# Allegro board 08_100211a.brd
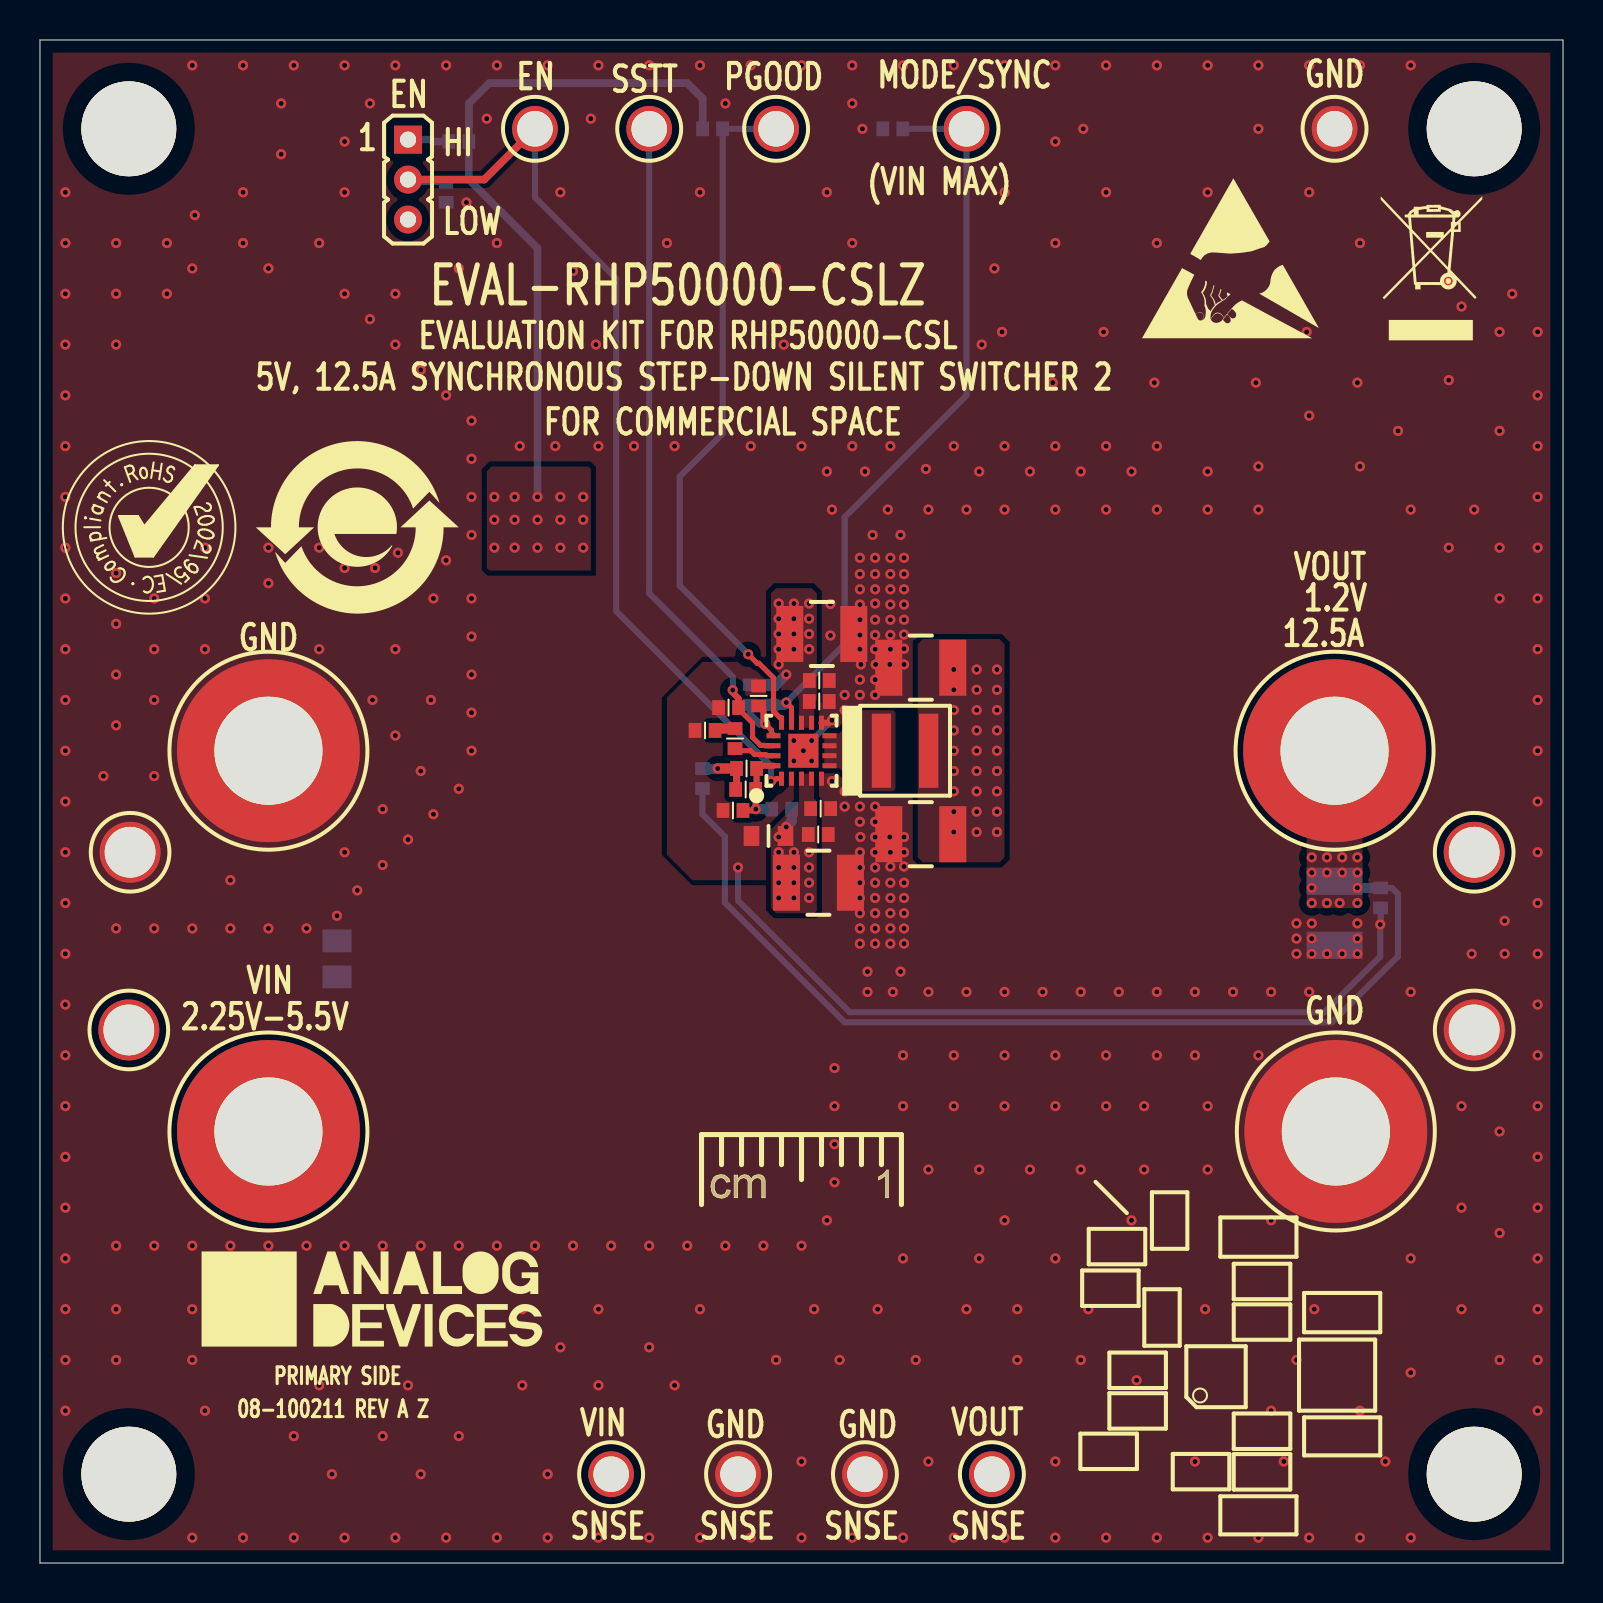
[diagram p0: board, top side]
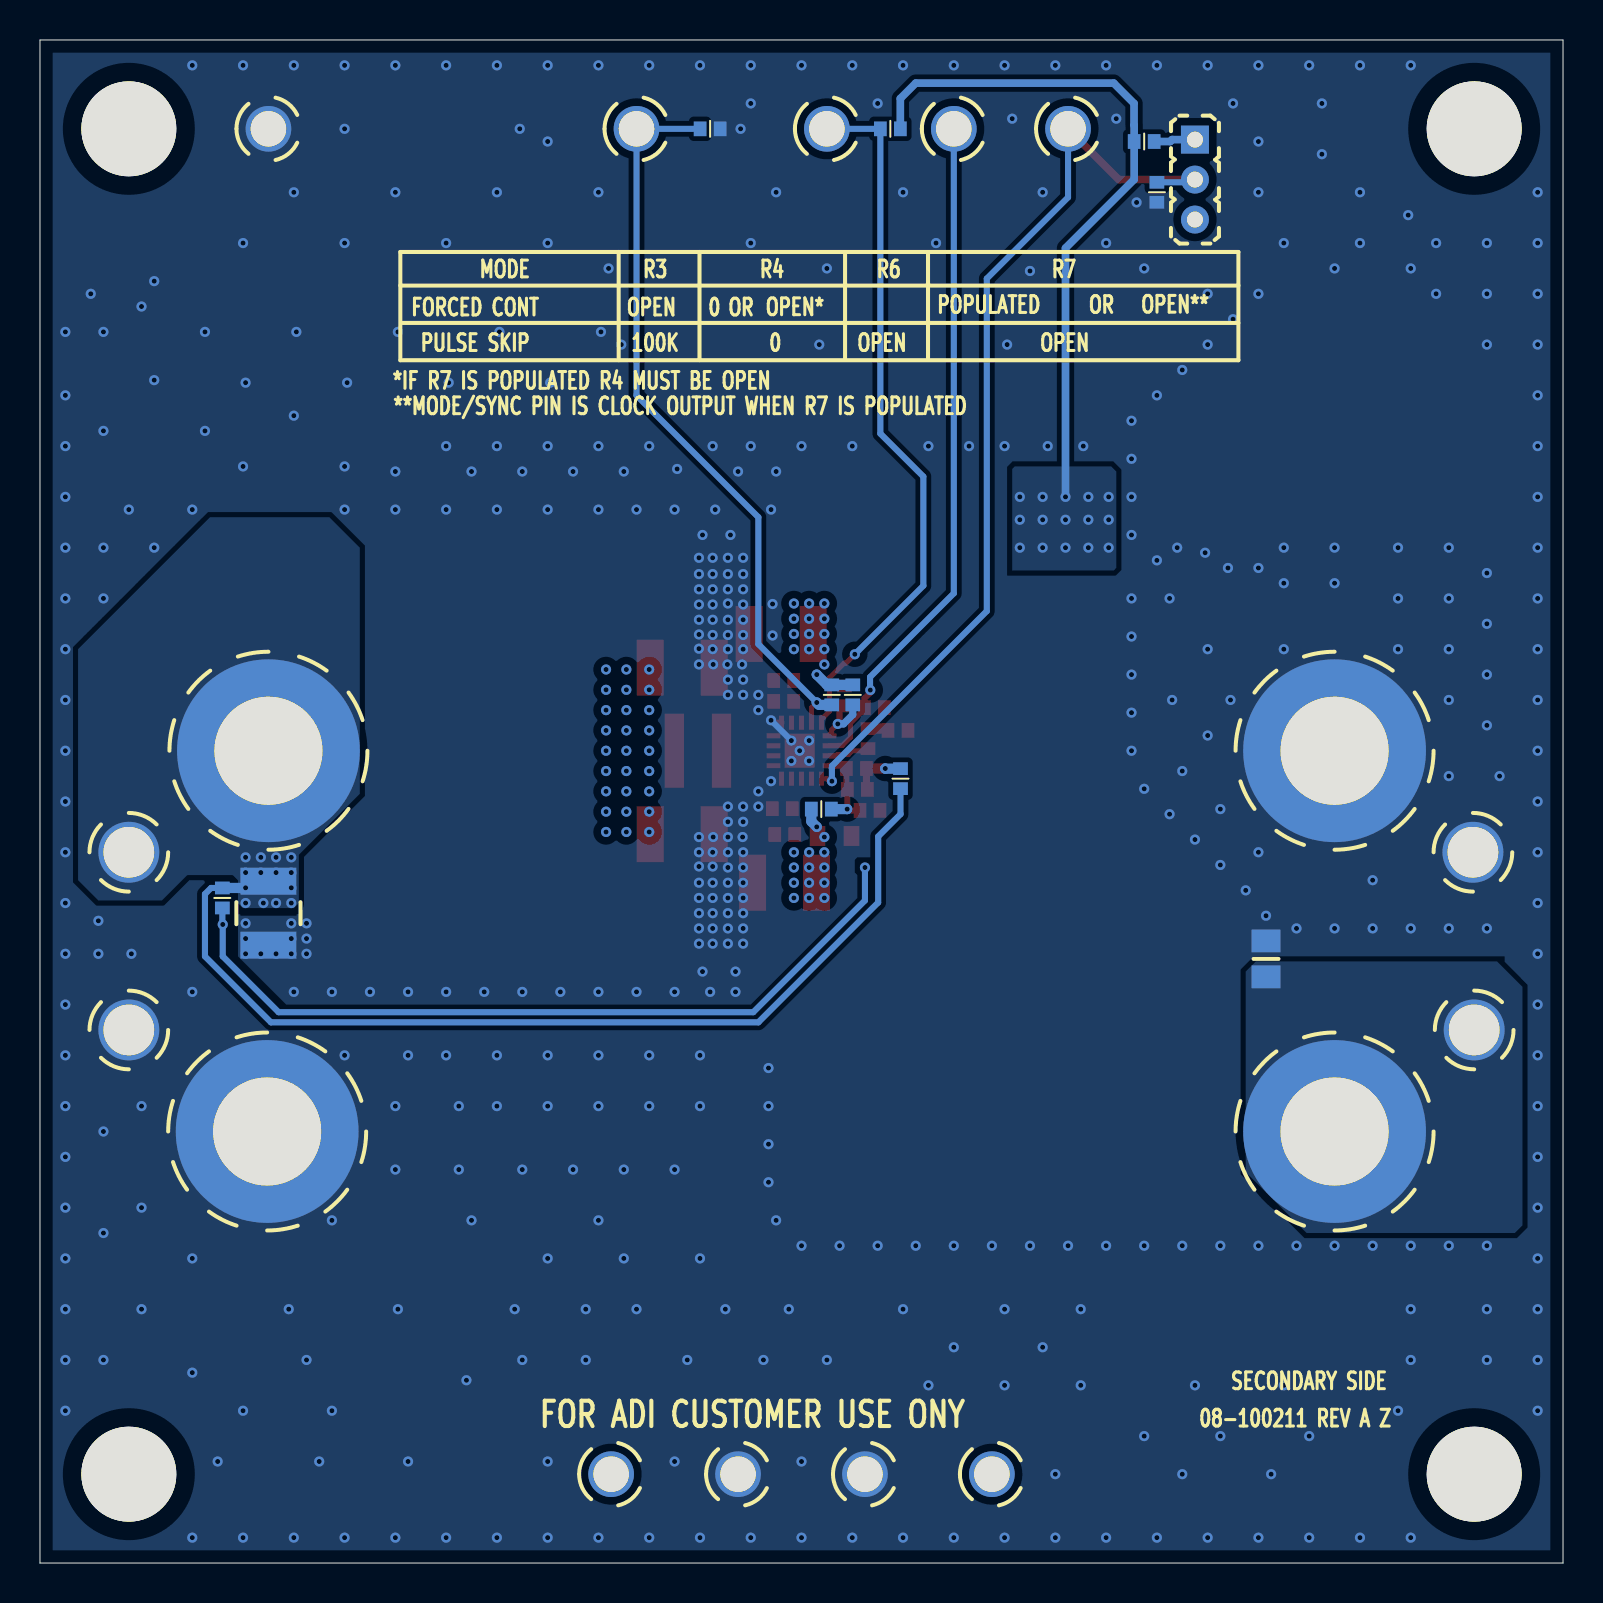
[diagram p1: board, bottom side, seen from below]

Outline 76.2 x 76.2 mm; copper layers: TOP, INTERNAL2, INTERNAL3, BOTTOM. Coordinates in mm from the lower left corner of the outline.
Outline path: 0,76.2 76.2,76.2 76.2,0 0,0 0,76.2

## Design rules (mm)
constraint set DEFAULT: min track width 0.254

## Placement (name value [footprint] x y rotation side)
C2  22UF  [CAP_1210_H110]  38.95 34.04 0 top
C3  22UF  [CAP_1210_H110]  39.12 46.48 0 top
C4  6.8PF  [CAP_0402]  35.31 38.7 0 top
C5  47UF  [CAP_1210_H110]  44.07 44.8 180 top
C6  47UF  [CAP_1210_H110]  44.07 36.46 180 top
C7  0.1UF  [CAP_0402]  67.08 33.27 270 bottom
C8  47UF  [CAP_1210_H110]  64.77 32.51 270 bottom
C9  0.033UF  [CAP_0402]  34.45 42.8 180 top
C11  470PF  [CAP_0402]  33.27 41.66 180 top
C16  10UF  [CAP_0805_H56]  14.86 30.23 90 bottom
C19  0.22UF  [CAP_0402]  38.94 36.45 0 top
C20  0.22UF  [CAP_0402]  38.99 44.15 0 top
C21  1UF  [CAP_0603_H41]  36.45 36.38 180 top
C22  0.1UF  [CAP_0402]  39.06 37.74 0 top
C23  0.1UF  [CAP_0402]  38.99 43.1 0 top
E1  2308-2-00-80-00-00-07-0  [CON_MILMX_2308-2-00-80-00-00-07-0]  46.35 71.75 0 top
E2  2308-2-00-80-00-00-07-0  [CON_MILMX_2308-2-00-80-00-00-07-0]  64.77 71.75 0 top
E3  2308-2-00-80-00-00-07-0  [CON_MILMX_2308-2-00-80-00-00-07-0]  28.57 4.45 0 top
E4  2501-2-00-80-00-00-07-0  [CON_MILMX_2501-2-00-80-00-00-07-0]  4.45 26.67 0 top
E5  2308-2-00-80-00-00-07-0  [CON_MILMX_2308-2-00-80-00-00-07-0]  47.62 4.45 0 top
E6  575-4  [CON_KEYST_575-4]  11.43 21.59 0 top
E7  2501-2-00-80-00-00-07-0  [CON_MILMX_2501-2-00-80-00-00-07-0]  71.75 35.56 0 top
E8  575-4  [CON_KEYST_575-4]  64.77 40.64 0 top
E9  575-4  [CON_KEYST_575-4]  11.43 40.64 0 top
E10  2501-2-00-80-00-00-07-0  [CON_MILMX_2501-2-00-80-00-00-07-0]  4.51 35.56 0 top
E11  575-4  [CON_KEYST_575-4]  64.83 21.59 0 top
E12  2308-2-00-80-00-00-07-0  [CON_MILMX_2308-2-00-80-00-00-07-0]  34.92 4.45 0 top
E13  2501-2-00-80-00-00-07-0  [CON_MILMX_2501-2-00-80-00-00-07-0]  71.75 26.67 0 top
E14  2308-2-00-80-00-00-07-0  [CON_MILMX_2308-2-00-80-00-00-07-0]  41.27 4.45 0 top
E15  2308-2-00-80-00-00-07-0  [CON_MILMX_2308-2-00-80-00-00-07-0]  24.77 71.75 0 top
E16  2308-2-00-80-00-00-07-0  [CON_MILMX_2308-2-00-80-00-00-07-0]  30.48 71.75 0 top
E17  2308-2-00-80-00-00-07-0  [CON_MILMX_2308-2-00-80-00-00-07-0]  36.83 71.75 0 top
J1  62000311121  [CON_WUREL_62000311121]  18.41 71.21 270 top
L1  0.1UH  [IND_1616_H122]  43.28 40.64 0 top
MECH1  9032  [ACC_KEYST_9032]  4.45 71.75 180 bottom
MECH2  9032  [ACC_KEYST_9032]  71.75 71.75 180 bottom
MECH3  9032  [ACC_KEYST_9032]  4.45 4.45 180 bottom
MECH4  9032  [ACC_KEYST_9032]  71.75 4.45 180 bottom
NOREF  -  []  4.45 4.45 0 top
NOREF#2  -  []  43.81 157.48 0 top
NOREF#3  -  []  16.64 13.21 0 top
NOREF#4  -  []  38.73 157.48 0 top
NOREF#5  -  []  93.98 79.41 0 top
NOREF#6  -  []  -263.53 -262.89 0 top
NOREF#7  -  []  76.2 0 90 top
NOREF#8  -  []  15.88 51.82 0 top
NOREF#9  -  []  76.2 0 0 top
NOREF#10  -  []  69.57 65.67 0 top
NOREF#11  -  []  4.45 4.45 0 top
NOREF#12  -  []  -263.53 -262.89 0 top
NOREF#13  -  []  46.65 -3.17 0 top
NOREF#14  -  []  -2.73 2.5 0 top
NOREF#15  -  []  0 0 0 top
NOREF#16  -  []  59.83 64.06 0 top
NOREF#17  -  []  0 0 0 top
NOREF#18  -  []  0 76.2 0 top
NOREF#19  -  []  70.49 81.38 0 top
NOREF#20  -  []  74.17 73.66 0 top
NOREF#21  -  []  5.46 51.82 0 top
R1  1M  [RES_0402]  20.96 71.12 180 bottom
R2  249K  [RES_0402]  20.32 68.58 270 bottom
R3  0  [RES_0402]  36.58 43.43 270 bottom
R4  0  [RES_0402]  35.53 43.43 270 bottom
R5  0  [RES_0402]  37.11 37.72 180 bottom
R6  100K  [RES_0402]  42.67 71.75 180 bottom
R7  0  [RES_0402]  35.95 43.38 90 top
R8  20  [RES_0402]  33.15 39.24 90 bottom
R9  140K  [RES_0402]  35.35 39.75 0 top
R10  100K  [RES_0402]  34.67 37.65 180 top
R11  100K  [RES_0402]  33.66 71.75 0 bottom
R12  15K  [RES_0402]  34.77 41.25 90 top
U1  RHP50000IV-CSL#TRPBF  [NC_AD_QFN0-50P_3-00X3-00X1-03_18_EP1-70X1-51]  38.1 40.64 90 top

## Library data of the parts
C2 C3 C5 C6 C8 = CAPACITOR_NP: alternate symbols: ()
C4 C7 C9 C11 C19 C20 C22 C23 = CAPACITOR_NP: alternate symbols: (CAP_0402_FF,CAP_0402_L)
C16 = CAPACITOR_NP: alternate symbols: (CAP_0805_H56_FF,CAP_0805_H56_L)
C21 = CAPACITOR_NP: alternate symbols: (CAP_0603_H41_FF,CAP_0603_H41_L)
E1-E17 = CON_TP_1P: alternate symbols: ()
J1 = CON_3P: alternate symbols: ()
L1 = INDUCTOR: alternate symbols: ()
MECH1-MECH4 = STAND_OFF: alternate symbols: ()
R1-R12 = RESISTOR_SMD: alternate symbols: (RES_0402_FF,RES_0402_L)
U1 = NC_RHP50000: alternate symbols: ()

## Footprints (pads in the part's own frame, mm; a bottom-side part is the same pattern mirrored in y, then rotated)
ACC_KEYST_9032
  round 4.75 hole 4.75 unplated: (0,0)
CAP_0402
  rect 0.635x0.737 smd: 1(-0.5,0) 2(0.5,0)
CAP_0603_H41
  rect 0.787x0.991 smd: 1(-0.85,0) 2(0.85,0)
CAP_0805_H56
  rect 1.143x1.448 smd: 1(-0.9,0) 2(0.9,0)
CAP_1210_H110
  rect 1.35x2.8 smd: 1(-1.6,0) 2(1.6,0)
CON_KEYST_575-4
  round 9.144 hole 5.41: 1(0,0)
CON_MILMX_2308-2-00-80-00-00-07-0
  round 2.286 hole 1.778: 1(0,0)
CON_MILMX_2501-2-00-80-00-00-07-0
  round 3.048 hole 2.54: 1(0,0)
CON_WUREL_62000311121
  rect 1.4x1.4 hole 0.8: 1(0,0)
  round 1.4 hole 0.8: 2(2,0) 3(4,0)
IND_1616_H122
  rect 0.965x3.708 smd: 1(-1.181,0) 2(1.181,0)
NC_AD_QFN0-50P_3-00X3-00X1-03_18_EP1-70X1-51
  rect 0.7x0.25 smd: 1(-1.4,1) 2(-1.4,0.5) 3(-1.4,0) 4(-1.4,-0.5) 5(-1.4,-1) 10(1.4,-1) 11(1.4,-0.5) 12(1.4,0) 13(1.4,0.5) 14(1.4,1)
  rect 0.25x0.7 smd: 6(-0.75,-1.4) 7(-0.25,-1.4) 8(0.25,-1.4) 9(0.75,-1.4) 15(0.75,1.4) 16(0.25,1.4) 17(-0.25,1.4) 18(-0.75,1.4)
  rect 1.7x1.51 smd: 19(0,-0.095)
RES_0402
  rect 0.635x0.737 smd: 1(-0.5,0) 2(0.5,0)

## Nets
GND_A: C2.2(N2) C3.2(N2) C5.2(N2) C6.2(N2) C7.2(N2) C8.2(N2) C9.2(N2) C11.2(N2) C16.2(N2) C19.2(N2) C20.2(N2) C21.2(N2) C22.2(N2) C23.2(N2) E2.1(N1) E9.1(N1) E10.1(N1) E11.1(N1) E12.1(N1) E13.1(N1) E14.1(N1) R2.2(N2) R6.2(N2) R7.2(N2) R10.2(N2) U1.2 U1.5 U1.10 U1.19
VIN: C2.1 C3.1 C16.1 C19.1 C20.1 C21.1 C22.1 C23.1 E3.1(N1) E4.1(N1) E6.1(N1) R1.1 R3.1 R4.1 R5.1 R11.1 U1.3 U1.4 U1.11 U1.12(VIN_4)
_N13: C11.1 R12.2(N2)
_N14: C4.1 R8.2(N2) R9.1
_N37: J1.1 R1.2(N2)
_N61: L1.1 U1.6 U1.7 U1.8 U1.9
_N64: R12.1 U1.17
EN: E15.1(N1) J1.2 R2.1 U1.1
MODE: E1.1(N1) R3.2(N2) R6.1 U1.13
PGOOD: E17.1(N1) R11.2(N2) U1.14
RT: R4.2(N2) R7.1 U1.15
SSTT: C9.1 E16.1(N1) U1.16
VFB: C4.2(N2) R5.2(N2) R9.2(N2) R10.1 U1.18
VOUT: C5.1 C6.1 C7.1 C8.1 E5.1(N1) E7.1(N1) E8.1(N1) L1.2(N2) R8.1

Pads without a net: J1 3

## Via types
v1: diameter 0.508, hole 0.254, TOP to BOTTOM, 570 vias

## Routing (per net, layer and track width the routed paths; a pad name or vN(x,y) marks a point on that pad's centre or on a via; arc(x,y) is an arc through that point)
GND_A: length 44.4
  TOP w0.305: v1(38.61,40.13) 38.19,40.55 38.19,40.61 ; 38.19,40.61 v1(38.19,40.64) 38.19,40.67 ; 38.19,40.61 v1(37.72,40.13) ; 38.19,40.67 38.19,40.73 v1(38.61,41.15) ; 38.19,40.67 v1(37.72,41.15) ; v1(39.62,42.16) 39.5,42.04 U1.10
  BOTTOM w0.305: v1(34.92,34.8) 34.92,33.15 40.51,27.56 64.26,27.56 67.06,30.35 v1(67.06,31.95) 67.08,31.97 C7.2 ; v1(38.61,41.15) v1(39.62,42.16)
  vias: v1(1.27,68.58) v1(1.27,66.04) v1(1.27,63.5) v1(1.27,60.96) v1(1.27,58.42) v1(1.27,55.88) v1(1.27,53.34) v1(1.27,50.8) v1(1.27,48.26) v1(1.27,45.72) v1(1.27,43.18) v1(1.27,40.64) v1(1.27,38.1) v1(1.27,35.56) v1(1.27,33.02) v1(1.27,30.48) v1(1.27,27.94) v1(1.27,25.4) v1(1.27,22.86) v1(1.27,20.32) v1(1.27,17.78) v1(1.27,15.24) v1(1.27,12.7) v1(1.27,10.16) v1(1.27,7.62) v1(3.18,39.37) v1(3.81,66.04) v1(3.81,63.5) v1(3.81,60.96) v1(3.81,49.53) v1(3.81,46.99) v1(3.81,44.45) v1(3.81,41.91) v1(3.81,31.75) v1(3.81,15.88) v1(3.81,12.7) v1(3.81,10.16) v1(5.71,50.8) v1(5.71,48.26) v1(5.71,45.72) v1(5.71,43.18) v1(5.71,39.37) v1(5.71,31.75) v1(5.71,15.88) v1(6.35,66.04) v1(6.35,63.5) v1(7.62,74.93) v1(7.62,64.77) v1(7.62,31.75) v1(7.62,15.88) v1(7.62,12.7) v1(7.62,10.16) v1(7.62,1.27) v1(7.75,67.44) v1(8.26,50.8) v1(8.26,48.26) v1(8.26,45.72) v1(8.26,7.62) v1(9.53,34.16) v1(9.53,31.75) v1(9.53,15.88) v1(10.16,74.93) v1(10.16,68.58) v1(10.16,66.04) v1(10.16,1.27) v1(11.43,64.77) v1(11.43,50.8) v1(11.43,49.02) v1(11.43,31.75) v1(11.43,15.88) v1(12.07,73.03) v1(12.07,70.49) v1(12.7,74.93) v1(12.7,6.35) v1(12.7,1.27) v1(13.34,31.75) v1(13.34,15.88) v1(13.97,66.04) v1(13.97,50.8) v1(13.97,49.02) v1(13.97,45.72) v1(13.97,8.89) v1(14.61,4.45) v1(14.86,32.39) v1(15.24,74.93) v1(15.24,71.12) v1(15.24,68.58) v1(15.24,63.5) v1(15.24,49.78) v1(15.24,35.56) v1(15.24,15.88) v1(15.24,1.27) v1(15.88,33.66) v1(16.51,73.03) v1(16.51,62.23) v1(16.64,43.18) v1(16.76,49.78) v1(17.14,37.72) v1(17.14,34.92) v1(17.14,15.88) v1(17.14,6.35) v1(17.78,74.93) v1(17.78,63.5) v1(17.78,60.96) v1(17.78,45.72) v1(17.78,41.4) v1(17.78,1.27) v1(17.91,50.55) v1(18.41,36.2) v1(18.41,8.89) v1(19.05,59.69) v1(19.05,39.62) v1(19.05,15.88) v1(19.05,4.45) v1(19.3,50.8) v1(19.56,43.18) v1(19.69,48.26) v1(19.69,37.47) v1(20.32,74.93) v1(20.32,58.42) v1(20.32,50.16) v1(20.32,1.27) v1(20.96,64.77) v1(20.96,38.73) v1(20.96,15.88) v1(20.96,6.35) v1(21.34,68.07) v1(21.59,57.15) v1(21.59,55.24) v1(21.59,53.34) v1(21.59,51.44) v1(21.59,48.26) v1(21.59,46.35) v1(21.59,44.45) v1(21.59,42.55) v1(21.59,40.64) v1(22.35,72.26) v1(22.86,74.93) v1(22.86,66.04) v1(22.86,15.88) v1(22.86,1.27) v1(24,55.88) v1(24.13,12.7) v1(24.13,8.89) v1(24.77,15.88) v1(25.4,74.93) v1(25.4,4.45) v1(25.4,1.27) v1(25.78,55.88) v1(26.04,68.58) v1(26.04,10.79) v1(26.67,64.64) v1(26.67,15.88) v1(27.56,72.26) v1(27.81,60.96) v1(27.94,74.93) v1(27.94,55.88) v1(27.94,12.7) v1(27.94,8.89) v1(27.94,1.27) v1(28.57,15.88) v1(29.72,55.88) v1(30.48,74.93) v1(30.48,15.88) v1(30.48,10.79) v1(30.48,1.27) v1(31.37,66.04) v1(31.75,55.88) v1(31.75,8.89) v1(32.39,15.88) v1(33.02,74.93) v1(33.02,68.58) v1(33.02,12.7) v1(33.02,1.27) v1(34.29,73.03) v1(34.29,15.88) v1(35.56,74.93) v1(35.56,55.88) v1(35.56,1.27) v1(36.2,15.88) v1(36.83,64.77) v1(36.83,10.16) v1(37.21,60.96) v1(38.1,74.93) v1(38.1,55.88) v1(38.1,15.88) v1(38.1,5.08) v1(38.1,1.27) v1(38.73,12.7) v1(39.37,68.58) v1(39.37,54.61) v1(39.37,17.14) v1(39.55,47.98) v1(39.55,46.41) v1(39.62,52.7) v1(39.62,39.12) v1(39.75,24.77) v1(39.75,22.86) v1(39.75,20.96) v1(39.75,19.05) v1(40.01,10.16) v1(40.26,43.43) v1(40.26,42.67) v1(40.26,38.61) v1(40.26,37.85) v1(40.64,74.93) v1(40.64,73.03) v1(40.64,66.04) v1(40.64,55.88) v1(40.64,1.27) v1(41.02,50.29) v1(41.02,49.48) v1(41.02,48.72) v1(41.02,47.96) v1(41.02,47.19) v1(41.02,46.43) v1(41.02,45.72) v1(41.07,44.96) v1(41.02,44.2) v1(41.02,43.43) v1(41.02,37.85) v1(41.02,37.08) v1(41.05,36.32) v1(41.02,35.56) v1(41.02,34.8) v1(41.02,34.04) v1(41.02,33.27) v1(41.02,32.51) v1(41.02,31.75) v1(41.02,30.99) v1(41.15,71.75) v1(41.27,54.61) v1(41.4,29.59) v1(41.4,28.57) v1(41.66,51.44) v1(41.78,50.29) v1(41.78,49.48) v1(41.78,48.72) v1(41.78,48.01) v1(41.78,47.19) v1(41.78,46.43) v1(41.78,45.72) v1(41.78,44.2) v1(41.78,43.43) v1(41.78,37.85) v1(41.78,37.08) v1(41.78,36.32) v1(41.78,35.56) v1(41.78,34.8) v1(41.78,34.04) v1(41.78,33.27) v1(41.78,32.51) v1(41.78,31.75) v1(41.78,30.99) v1(41.81,44.96) v1(41.91,12.7) v1(42.42,52.7) v1(42.55,55.88) v1(42.55,50.29) v1(42.55,49.48) v1(42.55,48.72) v1(42.55,47.96) v1(42.55,47.19) v1(42.55,46.43) v1(42.55,45.72) v1(42.52,44.96) v1(42.52,36.32) v1(42.55,35.56) v1(42.55,34.85) v1(42.55,34.04) v1(42.55,33.27) v1(42.55,32.51) v1(42.55,31.75) v1(42.55,30.99) v1(42.67,28.57) v1(43.05,51.44) v1(43.05,29.59) v1(43.18,74.93) v1(43.18,25.4) v1(43.18,22.86) v1(43.18,15.24) v1(43.18,1.27) v1(43.23,50.29) v1(43.23,49.48) v1(43.23,48.72) v1(43.23,47.96) v1(43.23,47.19) v1(43.23,46.46) v1(43.23,45.75) v1(43.23,44.96) v1(43.23,36.32) v1(43.23,35.56) v1(43.23,34.85) v1(43.23,34.04) v1(43.23,33.27) v1(43.23,32.51) v1(43.23,31.75) v1(43.23,30.99) v1(43.81,10.16) v1(44.32,54.74) v1(44.45,52.7) v1(44.45,28.57) v1(44.45,19.69) v1(44.45,5.08) v1(45.72,74.93) v1(45.72,55.88) v1(45.72,25.4) v1(45.72,22.86) v1(45.72,1.27) v1(46.35,52.7) v1(46.35,28.57) v1(46.35,12.7) v1(46.99,54.61) v1(46.99,19.69) v1(46.99,15.24) v1(47.12,60.96) v1(47.75,64.77) v1(48.13,61.59) v1(48.26,74.93) v1(48.26,68.58) v1(48.26,55.88) v1(48.26,52.7) v1(48.26,28.57) v1(48.26,25.4) v1(48.26,22.86) v1(48.26,17.14) v1(48.26,1.27) v1(48.9,12.7) v1(48.9,10.16) v1(49.53,54.61) v1(49.53,19.69) v1(50.16,28.57) v1(50.67,59.05) v1(50.8,74.93) v1(50.8,71.12) v1(50.8,66.04) v1(50.8,55.88) v1(50.8,52.7) v1(50.8,25.4) v1(50.8,22.86) v1(50.8,15.24) v1(50.8,5.08) v1(50.8,1.27) v1(52.07,54.61) v1(52.07,28.57) v1(52.07,19.69) v1(52.07,10.16) v1(52.2,71.75) v1(52.45,12.7) v1(53.21,61.59) v1(53.34,74.93) v1(53.34,68.58) v1(53.34,55.88) v1(53.34,52.7) v1(53.34,25.4) v1(53.34,22.86) v1(53.34,1.27) v1(53.98,28.57) v1(54.61,54.61) v1(54.61,17.14) v1(54.86,9.14) v1(55.24,22.86) v1(55.24,19.69) v1(55.75,59.05) v1(55.88,74.93) v1(55.88,66.04) v1(55.88,55.88) v1(55.88,52.7) v1(55.88,28.57) v1(55.88,25.4) v1(55.88,1.27) v1(57.79,28.57) v1(57.79,25.4) v1(57.79,5.08) v1(58.29,61.59) v1(58.29,12.7) v1(58.42,74.93) v1(58.42,68.58) v1(58.42,54.61) v1(58.42,52.7) v1(58.42,22.86) v1(58.42,19.69) v1(58.42,1.27) v1(59.69,28.57) v1(60.83,59.05) v1(60.96,74.93) v1(60.96,71.75) v1(60.96,66.04) v1(60.96,54.86) v1(60.96,52.7) v1(60.96,25.4) v1(60.96,1.27) v1(61.59,28.57) v1(61.59,17.14) v1(61.59,7.62) v1(62.23,5.08) v1(62.87,32) v1(62.87,31.24) v1(62.87,30.48) v1(62.87,10.16) v1(63.37,61.59) v1(63.5,74.93) v1(63.5,68.58) v1(63.5,57.4) v1(63.5,28.57) v1(63.5,1.27) v1(63.63,32) v1(63.63,31.24) v1(63.63,30.48) v1(63.75,12.7) v1(64.39,30.48) v1(65.15,30.48) v1(65.91,59.05) v1(65.91,32) v1(65.91,31.24) v1(65.91,30.48) v1(66.04,74.93) v1(66.04,66.04) v1(66.04,54.86) v1(66.04,7.62) v1(66.04,1.27) v1(67.31,5.08) v1(67.94,61.59) v1(67.94,56.64) v1(68.58,74.93) v1(68.58,52.7) v1(68.58,28.57) v1(68.58,15.24) v1(68.58,9.53) v1(68.58,1.27) v1(70.49,64.13) v1(70.49,59.18) v1(70.49,50.8) v1(71.12,62.87) v1(71.12,22.86) v1(71.12,17.78) v1(71.12,12.7) v1(71.63,30.48) v1(71.75,52.7) v1(73.03,61.59) v1(73.03,56.64) v1(73.03,50.8) v1(73.03,48.26) v1(73.03,21.59) v1(73.03,16.51) v1(73.03,10.16) v1(73.28,32.13) v1(73.28,30.48) v1(73.66,63.5) v1(74.93,61.59) v1(74.93,58.42) v1(74.93,55.88) v1(74.93,53.34) v1(74.93,50.8) v1(74.93,48.26) v1(74.93,45.72) v1(74.93,43.18) v1(74.93,40.64) v1(74.93,38.1) v1(74.93,35.56) v1(74.93,33.02) v1(74.93,30.48) v1(74.93,27.94) v1(74.93,25.4) v1(74.93,22.86) v1(74.93,20.32) v1(74.93,17.78) v1(74.93,15.24) v1(74.93,12.7) v1(74.93,10.16) v1(74.93,7.62)
VIN: length 78.2
  INTERNAL2 w0.305: v1(37.34,36.83) 38.73,36.83 39.37,36.2 39.37,28.57 41.27,26.67 41.27,17.14 E3.1
  BOTTOM w0.381: v1(24.89,53.34) 24.89,65.79 21.46,69.22 R1.1 21.46,71.93 21.46,71.94 21.46,73.03 22.48,74.04 32.39,74.04 33.15,73.27 R11.1
  BOTTOM w0.508: R5.1 37.61,37.1 v1(37.34,36.83) ; v1(37.34,44.45) 36.82,43.93 R3.1 R4.1
  vias: v1(22.73,53.34) v1(22.73,52.2) v1(22.73,50.8) v1(23.75,53.34) v1(23.75,52.2) v1(23.75,50.8) v1(24.89,52.2) v1(24.89,50.8) v1(26.04,53.34) v1(26.04,52.2) v1(26.04,50.8) v1(27.18,53.34) v1(27.18,52.2) v1(27.18,50.8) v1(36.96,48.01) v1(36.96,47.24) v1(36.96,46.48) v1(36.96,45.72) v1(36.96,44.96) v1(36.96,36.32) v1(36.96,35.56) v1(36.96,34.8) v1(36.96,34.04) v1(36.96,33.27) v1(37.72,48.01) v1(37.72,47.24) v1(37.72,46.48) v1(37.72,45.72) v1(37.72,35.56) v1(37.72,34.8) v1(37.72,34.04) v1(37.72,33.27) v1(38.48,48.01) v1(38.48,47.24) v1(38.48,46.48) v1(38.48,45.72) v1(38.48,35.56) v1(38.48,34.8) v1(38.48,34.04) v1(38.48,33.27)
_N13: length 1
  TOP w0.508: C11.1 34,41.75 R12.2
_N14: length 2.8
  TOP w0.356: R9.1 34.85,38.75 C4.1
  TOP w0.508: R9.1 v1(33.91,39.75)
  BOTTOM w0.508: v1(33.91,39.75) 33.9,39.74 R8.2
_N37: length 2.1
  BOTTOM w0.381: J1.1 19.56,71.21 19.65,71.12 R1.2
_N64: length 2.1
  TOP w0.254: R12.1 35.01,40.64 35.56,40.64 35.75,40.45 36.31,40.45 36.37,40.39 U1.17
EN: length 47.5
  TOP w0.254: v1(36.58,39.12) 36.7,39.12 36.83,39.24 U1.1
  TOP w0.381: J1.2 22.23,69.22 E15.1
  BOTTOM w0.305: E15.1 24.77,68.33 28.83,64.26 28.83,47.62 36.58,39.88 36.58,39.78 36.58,39.78 v1(36.58,39.12) ; J1.2 18.55,69.08 R2.1
MODE: length 37.5
  TOP w0.254: v1(37.34,43.05) 37.6,42.79 U1.13
  BOTTOM w0.305: v1(37.34,43.05) 40.26,45.97 40.26,52.32 46.35,58.42 E1.1 R6.1
  BOTTOM w0.508: R3.2 37.22,42.93 v1(37.34,43.05)
PGOOD: length 35.5
  TOP w0.254: U1.14 37.1,42.27 37.08,42.29 37.02,42.29 36.7,42.61 36.7,44.29 35.97,45.02 35.88,45.02 v1(35.43,45.47)
  BOTTOM w0.305: E17.1 R11.2 34.16,56.51 32,54.36 32,48.9 v1(35.43,45.47)
RT: length 3.3
  TOP w0.254: v1(36.29,41.98) 36.59,41.67 36.59,41.53 36.7,41.43 U1.15
  TOP w0.305: R7.1 36.2,42.69 36.2,42.07 v1(36.29,41.98)
  BOTTOM w0.356: R4.2 35.53,42.44 36,41.98 v1(36.29,41.98)
SSTT: length 33.8
  TOP w0.254: C9.1 34.95,42.73 35.65,42.03 35.65,41.31 36.06,40.91 36.26,40.91 36.27,40.89 U1.16
  TOP w0.305: C9.1 34.95,43.26 34.67,43.54 34.67,43.66 v1(34.66,43.68)
  BOTTOM w0.305: E16.1 30.48,48.51 34.67,44.32 34.67,43.69 v1(34.66,43.68)
VFB: length 4.4
  TOP w0.305: U1.18 35.99,39.89 R9.2 35.85,38.75 C4.2 35.81,37.73 v1(35.81,37.72) 35.75,37.65 R10.1
  BOTTOM w0.508: R5.2 v1(35.81,37.72)
VOUT: length 91.3
  INTERNAL2 w0.305: E5.1 47.62,13.72 61.47,27.56 65.02,27.56 67.72,30.25 67.72,32.99 66.93,33.78 v1(65.91,33.78)
  BOTTOM w0.305: R8.1 33.15,37.47 34.26,36.35 34.26,33.05 40.26,27.05 64.64,27.05 67.94,30.35 67.94,33.47 67.64,33.77 C7.1
  BOTTOM w0.508: C8.1 65.11,33.77 C7.1
  vias: v1(45.72,44.7) v1(45.72,43.69) v1(45.72,42.67) v1(45.72,41.66) v1(45.72,40.64) v1(45.72,39.62) v1(45.72,38.61) v1(45.72,37.59) v1(45.72,36.58) v1(46.86,44.7) v1(46.86,43.69) v1(46.86,42.67) v1(46.86,41.66) v1(46.86,40.64) v1(46.86,39.62) v1(46.86,38.61) v1(46.86,37.59) v1(46.86,36.58) v1(47.88,44.7) v1(47.88,43.69) v1(47.88,42.67) v1(47.88,41.66) v1(47.88,40.64) v1(47.88,39.62) v1(47.88,38.61) v1(47.88,37.59) v1(47.88,36.58) v1(63.63,35.31) v1(63.63,34.54) v1(63.63,33.78) v1(63.63,33.02) v1(64.39,35.31) v1(64.39,34.54) v1(64.39,33.02) v1(65.02,33.02) v1(65.15,35.31) v1(65.15,34.54) v1(65.91,35.31) v1(65.91,34.54) v1(65.91,33.02)

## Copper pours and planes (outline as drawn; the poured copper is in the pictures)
GND_A on TOP: 0.64,75.56 0.64,0.64 75.56,0.64 75.56,75.56 ; 1 cut-out
GND_A on BOTTOM: 0.64,75.56 0.64,0.64 75.56,0.64 75.56,75.56 ; 1 cut-out
GND_A on INTERNAL2: 0.64,75.56 0.64,0.64 75.56,0.64 75.56,75.56 ; 2 cut-outs
GND_A on INTERNAL2: 39.24,50.67 39.24,30.73 39.5,30.48 43.69,30.48 43.81,30.61 43.81,50.67 43.69,50.8 39.37,50.8
GND_A on INTERNAL3: 0.64,75.56 0.64,0.64 75.56,0.64 75.56,75.56
VIN on TOP: 38.61,48.77 36.83,48.77 36.58,48.51 36.58,44.83 37.08,44.32 37.08,43.69 37.34,43.43 37.59,43.43 37.97,43.05 37.97,41.78 38.73,41.78 38.73,43.05 38.86,43.18 38.86,48.51
VIN on TOP: 37.98,39.5 37.98,38.1 36.58,36.7 36.58,32.77 36.83,32.51 38.73,32.51 38.86,32.64 38.86,38.1 38.73,38.24 38.73,39.5
VIN on TOP, BOTTOM: 27.43,54.86 22.61,54.86 22.35,54.61 22.35,49.78 22.48,49.66 27.56,49.66 27.56,54.74
VIN on BOTTOM: 3.18,30.1 3.18,29.97 2.03,28.83 2.03,16.89 2.41,16.51 12.83,16.51 15.88,19.56 15.88,29.59 15.37,30.1
VIN on INTERNAL2: 14.48,30.99 3.05,30.99 1.91,29.84 1.91,17.02 2.41,16.51 37.85,16.51 38.99,17.65 38.99,53.59 37.72,54.86 22.61,54.86 22.35,54.61 22.35,38.86
_N61 on TOP: 39.24,41.52 39.24,39.76 39.99,39.76 41.15,38.61 42.67,38.61 42.8,38.73 42.8,42.55 42.67,42.67 41.15,42.67 39.99,41.52
VOUT on TOP: 43.92,45.97 43.92,35.31 44.17,35.05 48.01,35.05 48.26,35.31 48.26,45.97 48.01,46.23 44.17,46.23
VOUT on TOP: 61.85,43.56 61.85,37.85 63.37,36.32 63.37,32.89 63.5,32.77 65.91,32.77 66.17,33.02 66.17,36.45 67.82,38.1 67.82,43.56
VOUT on BOTTOM: 61.72,52.32 60.2,50.8 60.2,38.48 63.25,35.43 63.25,33.02 63.5,32.77 66.04,32.77 66.29,33.02 66.29,34.16 66.55,34.42 68.83,34.42 70.1,33.15 73.28,33.15 74.29,34.16 74.29,45.72 67.69,52.32
VOUT on INTERNAL2: 44.07,51.94 44.07,29.34 44.2,29.21 66.29,29.21 66.29,29.46 67.18,30.35 67.18,33.02 66.67,33.53 66.29,33.53 66.29,34.16 67.06,34.16 68.07,33.15 68.07,30.1 67.44,29.46 67.44,29.21 69.34,29.21 74.17,34.04 74.17,45.85 67.94,52.07 44.2,52.07

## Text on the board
Ref Des/Silkscreen Bottom: SECONDARY SIDE | 08-100211 REV A Z | OPEN** | OR | R7 | OPEN | POPULATED | R6 | 0 | OPEN* | R4 | R3 | 100K | MODE | PULSE SKIP | FORCED CONT | **MODE/SYNC PIN IS CLOCK OUTPUT WHEN R7 IS POPULATED | *IF R7 IS POPULATED R4 MUST BE OPEN | FOR ADI CUSTOMER USE ONY
Ref Des/Silkscreen Top: 08-100211 REV A Z | PRIMARY SIDE | 2.25V-5.5V | GND | VIN | 5V, 12.5A SYNCHRONOUS STEP-DOWN SILENT SWITCHER 2 | EN | EVALUATION KIT FOR RHP50000-CSL | HI | LOW | FOR COMMERCIAL SPACE | SNSE | SSTT | PGOOD | (VIN MAX) | MODE/SYNC | VOUT | 12.5A | 1.2V | EVAL-RHP50000-CSLZ
DIMENSION: (REF) | SEE NOTE 20 | " "
User.16: SCAN FOR INFO | THE PLASTIC PRESS-IN STANDOFF (4-PLCS). | DEFAULT MOUNTING HOLE IS FOR | KEEP CENTER OF STANDOFF HOLES 0.2" AWAY FROM BOARD EDGES | DEFAULT LOCATION FOR HARDWARE NAME | ADD TEXT UNDER QR CODE | MUST READ "SCAN FOR INFO" | DEFAULT QR CODE LOCATION | DEFAULT LOGO LOCATION
User.34: EVAL-RHP50000-CSLZ
User.37: FAB NOTES REVISION: FEBRUARY 21 2025 | 1.   DIMENSIONS ARE IN INCHES (EXCEPT WHERE NOTED). | ALL DOCUMENTS & SPECIFICATIONS REFERRED TO BELOW SHOULD BE THE LATEST REVISIONS. | 8.   IMPEDANCE REQUIREMENTS: IF NO STACKUP IS DEFINED, THE VENDOR IS ALLOWED TO ADJUST THE DIELECTRIC | 13.  PLATING SPECIFICATION: | 2.  BOARD MATERIAL: | 3.   ALL LAMINATES & BONDING MATERIALS SHOULD BE SELECTED FROM IPC-4101 OR IPC-4103,(TG>170 DEGC TD>300 DEGC) | 4.   REFER TO IPC-6010 SERIES, CLASS 2 FOR FABRICATION. | 5.   REFER TO LAMINATION DIAGRAM FOR OVERALL BOARD THICKNESS, TOLERANCE APPLIES AFTER ALL LAMINATION AND PLATING | 6.   BOW & TWIST NOT TO EXCEED 0.0075 INCHES (0.75%) PER LINEAR INCH AND SHOULD BE MEASURED PER IPC-TM-650, METHOD 2.4.22. | 7.   ACCEPTABILITY PER ADI SPECIFICATION TST00115. | 9.   FILLET OPTIONS TO ENHANCE RELIABILITY AT PAD JUNCTIONS WHERE SPACING PERMITS. | 10.  THIEVING: | 11.  LAYER TO LAYER REGISTRATION SHALL BE WITHIN 0.003 INCHES. | 12.  DRILL SIZES ARE FINISHED HOLE SIZES. ALL HOLES SHALL BE LOCATED WITHIN 0.005 INCHES DTP,UNLESS SPECIFIED. | 14.  SURFACE FINISH: | (USE CHECKED ITEMS) | PROCESSES. FINISHED THICKNESS MEASURED FROM TOP COPPER TO BOTTOM COPPER. | (X)  ISOLA 370HR OR EQUIVALENT | ( )  ISOLA-FR408HR OR EQUIVALENT | ( )  ISOLA IS410 | ( )  MEGTRON 6 | ( )  NELCO-4000-13 | ( )  ROGERS 4350B | ( )  ROGERS 3003 | ( )  OTHER ________________________ | ( ) FILLETS ALLOWED | (X) FILLETS NOT ALLOWED | ( ) VENDOR MAY ADD THIEVING TO COMPENSATE FOR LOW COPPER DENSITY AREAS MAINTAINING A MINIMUM | (X) VENDOR MAY NOT ADD THIEVING TO COMPENSATE FOR LOW COPPER DENSITY AREAS. | HINDER PROPER SOLDER WICKING. BARREL RELIEF ON SOLDERMASK ALLOWED IN UNFILLED VIA IN PAD HOLES. | (X) REFER TO LAMINATION DIAGRAM FOR FINISHED COPPER WEIGHT/THICKNESS REQUIRMENTS | (X) IMMERSION GOLD (ENIG) 1.58-3.94 MICRO INCHES OVER 118-236 MICRO INCHES MIN. OF ELECTROLESS NICKEL PER IPC-4552 | ( ) OSP (ORGANIC SOLDERABILITY PRESERVATIVE) | ( ) IMMERSION SILVER | ( ) SOFT WIRE BONDABLE GOLD 30-50 MICRO INCHES OF SOFT WIRE | ( ) EDGE CONNECTOR FINGERS ARE TO BE PLATED WITH 100 MICRO-INCHES(.0001") OF LOW STRESS | THICKNESS & TRACE WIDTHS TO MEET THE IMPEDANCE REQUIREMENT. IF SPECIFIED, THE VENDOR MUST | TRACE WIDTH & SPACING THAT IMPACT THE REQUIREMENTS MUST HAVE WRITTEN APPROVAL FROM ADI. | MINIMUM BARREL PLATING OF 0.001 INCHES. PLATED HOLES SHALL NOT BE ROUGH OR IRREGULAR SO AS TO | MEET THE REQUIREMENTS LISTED IN THE IMPEDANCE TABLE. ANY ADJUSTMENT MADE TO THE DEFINED STACKUP, | UL FLAMMABILITY RATING 94V-0. BOARD MATERIAL & CONSTRUCTION SHALL MEET THE REQUIREMENTS OF UL796/UL796F. | BONDABLE GOLD OVER 100-150 MICRO INCHES OF NICKEL | NICKEL UNDER 30 MICRO-INCHES (.0003') OF GOLD | 0.100 INCH CLEARANCE FROM ALL COPPER FEATURES, | THE STARTING COPPER WEIGHT/THICKNESS CAN VARY AS LONG AS THE FINISHED COPPER | WEIGHT/THICKNESS IS NOT LESS THAN THE SPECIFIED VALUE. | UNLESS OTHERWISE SPECIFIED | HOMOGENOUS MATERIALS IN THIS BOARD SHALL BE COMPLIANT WITH | WORKMANSHIP SHALL CONFORM TO IPC-A-600, CLASS 2. | THE EU RoHS DIRECTIVE 2002/95/EC | 21.  INTENTIONAL SHORTS: | 17.  FINAL ELECTRICAL TEST TO BE PERFORMED USING PROVIDED IPC-D-356A NETLIST OR ODB++ FORMAT FILE. | 22.  PEMNUTS: | 23.  MANUFACTURER TO ETCH/STAMP WITH PERMANENT NON-CONDUCTIVE INK ON BOTTOM | LEGEND LAYER. CREATE BOTTOM LEGEND IF LAYER NOT PRESENT. | 15.  SOLDERMASK: | 16.  APPLY SILKSCREEN TO BOTH SIDES USING A NON-CONDUCTIVE, EPOXY BASED INK PER ARTWORK. | 18.  A TIME DOMAIN REFLECTOMETER REPORT (TDR) FOR EACH IMPEDANCE CONTROLLED LAYER & A CERTIFICATE | 19.  IF PRESENT, ALL BLIND/BURIED VIAS WITH AN ASPECT RATIO <1:1 TO BE PLATED SHUT WITH COPPER WHEN | 20.  FOR VIA FILL INFORMATION REFER TO DRILL CHART: | (X) WHITE | ( ) OTHER__________ | IF AN INTENTIONAL SHORT REPORT IS SUPPLIED AND DOES NOT MATCH THE FAB DATA THEN | (X) LPI | COLOR | (X) GREEN | THE PCB SHALL HAVE A VERIFICATION STAMP. | (X)  NON-CONDUCTIVE EPOXY FILL ALL DRILLED VIAS | ( )  COPPER FILL ALL 0.XXXX INCHES DRILLED VIAS | ( )  PEMNUTS TO BE INSTALLED BY FABRICATOR.. | ( )  PEMNUTS NOT TO BE INSTALLED BY FABRICATOR. | (X)  NOT APPLICABLE. | USED AS VIA-IN-PAD OR AS A STACKED VIA. BLIND/BURIED VIAS WITH AN ASPECT RATIO >1:1 TO BE FILLED | A. UL CODE-FLAMMABILITY RATING FOR THOSE APPROVED MATERIALS(IF APPLICABLE) | B. DATE CODE | C. LOT NUMBER | D. MANUFACTURER LOGO | CAN'T BE PERFORMED BECAUSE THE TRACE LENGTH IS TOO SHORT ON THE OUTER LAYERS AT THE PIN ESCAPES | SOLDERMASK OVER BARE COPPER OR BARE GOLD (BOTH SIDES) TO MEET IPC-SM-840. | IF PRESENT,DO NOT MODIFY SOLDERMASK DEFINED PADS (MASK OPENINGS LESS THAN COPPER PAD) WITHOUT APPROVAL. | ADI APPROVAL IS REQUIRED. | OF COMPLIANCE SHALL BE PROVIDED BY VENDOR AT TIME OF SHIPMENT. INSTANCES WHERE TDR TESTING | WITH NON-CONDUCTIVE EPOXY. | MATERIAL: | NOTES: | TOOLING: | FINISH: | TESTING: | MISCELLANEOUS:
User.45: INSTALL STANDOFF (M130778) ON SECONDARY SIDE AT 4 PLACES. | MISCELLANEOUS: | 5. ASSEMBLY VENDOR SHALL PROVIDE A CERTIFICATE OF CONFORMANCE (COFC), | 6. ENVIROMENTAL REGULATIONS. ALL ASSEMBLED PCB'S SHALL CONFORM TO RoHS & REACH REGULATIONS WHICH MUST | 7. FOR ROHS COMPLIANCE THE BOARD SHOULD UNDEGO Pb-FREE SOLDERING. | 8. THE FINAL ASSEMBLED BOARDS SHALL BE FREE OF FLUX RESIDUE AND FOREIGN MATERIALS. | 1. ASSEMBLED BOARD ACCEPTABILITY SHALL BE PER IPC-A 601 CLASS 2 (LATEST REVISION). | 2. REPAIRS PER IPC-7711/21(LATEST REVISION) ARE ALLOWED. REPAIRS ARE NOT ALLOWED IN SOLDER MASK | 3. REFER TO TST00119 (LATEST REVISION) FOR ASSEMBLY SPECIFICATIONS. | 4. SPECIFIC COMPONENTS SHOULD BE INSTALLED WITH THEIR CORRESPONDING MECHANICAL PARTS LISTED ON THE | FREE AREA ON EITHER SIDE OF THE BOARD.UNLESS OTHERWISE SPECIFIED. | MECHANICAL PARTS SECTION OF THE BOM. | THE ITEMS BELOW SHOULD BE CARRIED OUT IF APPLICABLE AND REPORT SUPPLIED WITH THE ASSMBLED BOARDS. | X-RAY SHALL BE PERFORMED ON ALL BOTTOM TERMINATIONS. | INCIRCUIT FUNCTIONAL TEST WHEN REQUIRED. | IMAGES OF TOP & BOTTOM OF BOARD(INCLUDING DUT PADS). | CONFORM TO THE EU DIRECTIVES, REFER TO ADI DOCUMENT ADI1406. | INSTAL SHUNT CONNECTOR (M131884) TO JP1 PIN 1 AND 2 | FIGURE | SIZE | 10.0 | 31.5 | 70.0 | 100.0 | 213.0 | 187.01 | TOLERANCE | +3.0/-8.0 | +3.0/-3.0 | PLATED | NON-PLATED | ALL UNITS ARE IN MILS | QTY | 570 | 3 | 9 | 4 | NOTES | DRILL CHART: TOP to BOTTOM
